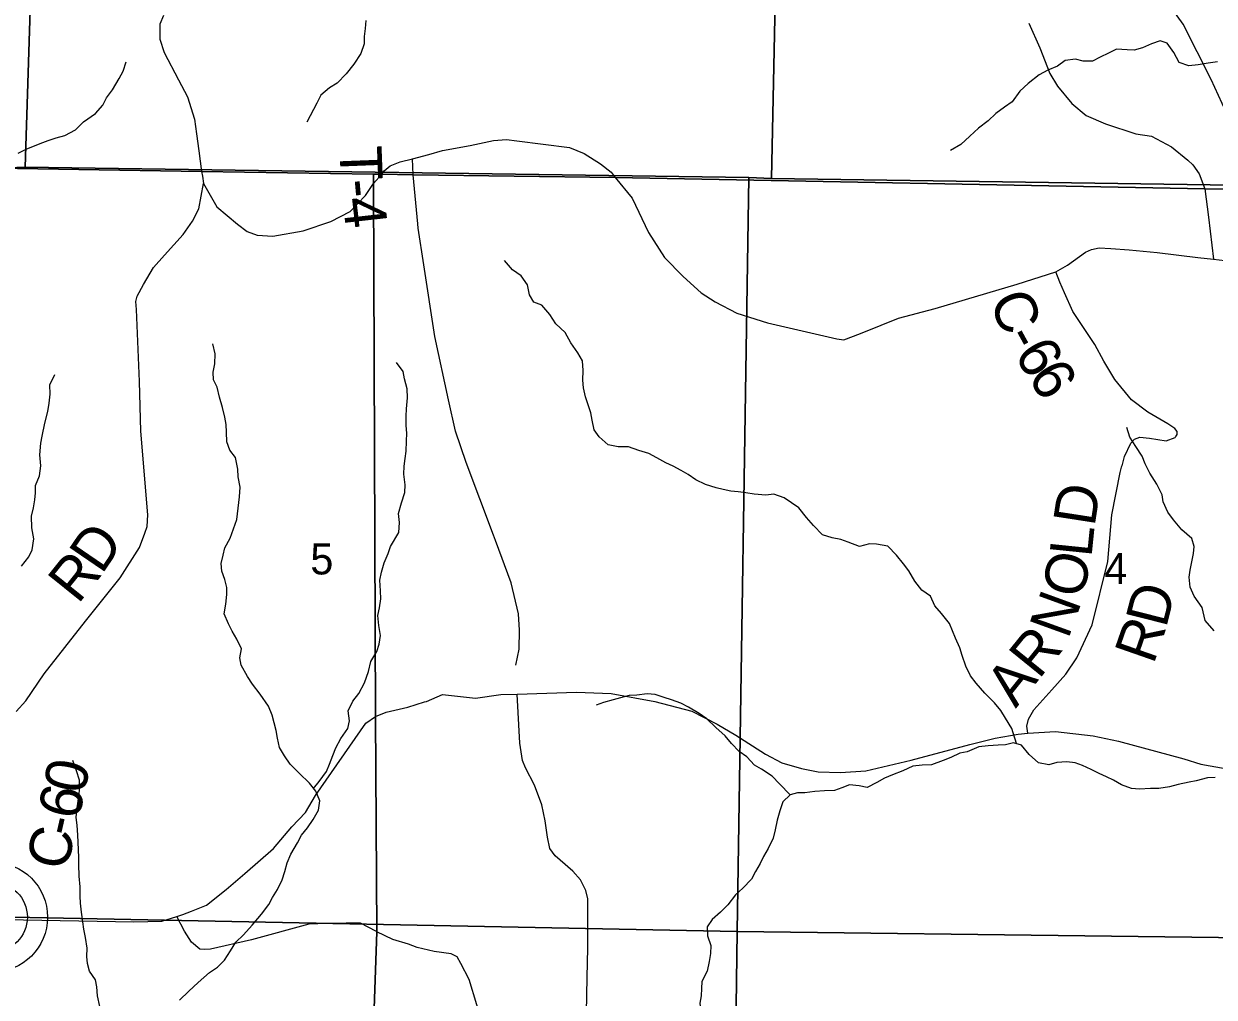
# Model space of a CAD drawing. Extents: x 2043100 to 2470832, y 443715 to 810583.
# Drawn here: x 2231654 to 2240142, y 633122 to 640063 of the extents above; entities that cross this region are included whole.
import ezdxf

# ---------------------------------------------------------------- set-up
doc = ezdxf.new("R2010")
doc.units = 0
for name, color, linetype in [('GM_X_County_Road', 7, 'Continuous'), ('GM_X_County_Road_Text', 7, 'Continuous'), ('GM_X_Interstate_Route', 7, 'Continuous'), ('GM_X_Minor_River', 7, 'Continuous'), ('GM_X_Section', 7, 'Continuous'), ('GM_X_Section_Text', 7, 'Continuous'), ('GM_X_State_Route', 7, 'Continuous'), ('GM_X_Township', 7, 'Continuous'), ('GM_X_Township_Road', 7, 'Continuous'), ('GM_X_Township_Road_Text', 7, 'Continuous'), ('GM_X_Township_ROW', 7, 'Continuous'), ('GM_X_Unincorporated', 7, 'Continuous')]:
    doc.layers.add(name, color=color, linetype=linetype)

msp = doc.modelspace()

# ---------------------------------------------------------------- linework, layer by layer
at = {"layer": 'GM_X_County_Road'}
for points in [[(2232651, 640122.8), (2232625.1, 640060.7), (2232625.1, 639952.5), (2232655.2, 639858.5), (2232757.3, 639664.4), (2232821.5, 639542.1), (2232870.3, 639383.6), (2232886.6, 639278.4), (2232902.9, 639157), (2232922, 639010.4), (2232927.4, 638975.8)], [(2234425.6, 639100.8), (2234542.6, 639130.9), (2234640.2, 639160.3), (2234837.2, 639195.1), (2235003.1, 639231.4), (2235097.1, 639237.6), (2235169.1, 639229.6), (2235544.8, 639180.6), (2235648.6, 639138.3), (2235765.6, 639064.4), (2235841.3, 639004.6), (2235869.8, 638968.1), (2235991.7, 638820.7), (2236108.1, 638575.9), (2236222.7, 638397.3), (2236356.7, 638261), (2236484.5, 638144.7), (2236583.5, 638080), (2236738.7, 638000.1), (2236957.9, 637931.2), (2237297.3, 637852), (2237451.9, 637816.2), (2237500, 637808.8), (2237619.5, 637854.6), (2237766.7, 637912.9), (2237892.1, 637962.8), (2238151.3, 638032.6), (2238737.3, 638205.4), (2239013, 638295.5), (2239094.8, 638342), (2239224.9, 638434.2), (2239266, 638453.3), (2239322.1, 638464.3), (2239405.5, 638461.5), (2239535.5, 638452), (2239735.3, 638431.4), (2240025.2, 638396.8)], [(2232935.3, 638924.7), (2233031.1, 638757.5), (2233176.9, 638633.4), (2233245.7, 638582.4), (2233318.2, 638555.4), (2233430.4, 638549), (2233646, 638586.2), (2233843.2, 638653.2), (2233982.3, 638725.3), (2234089.7, 638839.6), (2234148.8, 638924.2), (2234206.5, 638990.6), (2234223.2, 639013.9), (2234266.2, 639049.8), (2234336.6, 639079.9), (2234425.6, 639100.8)], [(2232927.4, 638975.8), (2232935.3, 638924.7)], [(2231601, 635159), (2231669.9, 635236.1), (2231799.3, 635428.3), (2232094.2, 635803.2), (2232342.1, 636111.3), (2232479.1, 636327.6), (2232517.7, 636430.4), (2232533, 636478.7), (2232539.8, 636560.9), (2232489.3, 637159.1), (2232478.3, 637511.5), (2232457, 638026), (2232454.2, 638082), (2232461.6, 638120.2), (2232508.5, 638205), (2232578.8, 638324.2), (2232657.6, 638413.5), (2232789.6, 638561.7), (2232856.4, 638654.8), (2232903.2, 638743.6), (2232935.3, 638924.7)], [(2240025.2, 638396.8), (2240136.2, 638383.5), (2240420.8, 638350.7), (2240473.8, 638314.4), (2240598, 638293), (2240718.1, 638275.5), (2240814.2, 638272)], [(2239867.4, 637119.6), (2239878.7, 637133.8), (2239878.6, 637155.9), (2239860.5, 637177.8), (2239810.3, 637211.6), (2239667.9, 637293.1), (2239553.4, 637382.7), (2239432.7, 637526.3), (2239354, 637658.2), (2239291.5, 637776), (2239134.3, 638011.7), (2239073.7, 638143.6), (2239041.3, 638219.5), (2239013, 638295.5)], [(2239484.6, 636910.4), (2239503.2, 636977.8), (2239546.8, 637072.2), (2239574.7, 637100.3), (2239610.6, 637116.5), (2239680.7, 637108.9), (2239798.8, 637089.4), (2239862.8, 637113.7), (2239866, 637117.7), (2239867.4, 637119.6)], [(2238812.9, 635004.9), (2238805.3, 635055.6), (2238817, 635103.7), (2238856.8, 635172), (2238984.2, 635312.8), (2239083.8, 635425.5), (2239163.3, 635542), (2239272.3, 635776.9), (2239384.4, 636228.1), (2239410.9, 636562.7), (2239471.6, 636863.5), (2239484.5, 636910.3), (2239484.6, 636910.4)]]:
    msp.add_lwpolyline(points, dxfattribs=at)
at = {"layer": 'GM_X_Interstate_Route'}
msp.add_lwpolyline([(2240394.7, 638771), (2240382.5, 638881.1), (2240303.2, 639267.5), (2240121.4, 639665.5), (2239921.6, 640061.4), (2239486.5, 640666.7), (2238945.3, 641275.5), (2238484.4, 641836.6), (2237995, 642501.7), (2237789.2, 642869.6), (2237609.2, 643317.8), (2237341.9, 644058.2), (2237167.9, 644510.4), (2236925.2, 645114.6), (2236607.5, 645943), (2236281.8, 646755.3), (2236081.5, 647271.5), (2235837.1, 647771.5), (2235579.2, 648157.2), (2235141.7, 648882.8), (2234805.3, 649336.2), (2234488.5, 649938.1), (2234352.9, 650290.3), (2234278.2, 650792.6)], dxfattribs=at)
at = {"layer": 'GM_X_Minor_River'}
for points in [[(2234093.6, 640087.2), (2234087.8, 640029.1), (2234082, 639973), (2234080.1, 639921), (2234056.3, 639850.8), (2234006.6, 639774.6), (2233952.8, 639706.4), (2233889, 639640.1), (2233833.2, 639605.9), (2233771.3, 639553.6), (2233743.5, 639497.5), (2233671.9, 639361.1)], [(2240164.3, 639792), (2240098.3, 639781.7), (2240028.4, 639769.5), (2239960.4, 639763.2), (2239892.4, 639787), (2239854.2, 639858.9), (2239806, 639924.8), (2239756, 639940.7), (2239694.1, 639920.4), (2239630.2, 639892.2), (2239572.3, 639874), (2239520.3, 639877.8), (2239444.3, 639881.5), (2239388.4, 639853.3), (2239328.5, 639825.1), (2239274.6, 639796.9), (2239208.6, 639796.7), (2239152.6, 639810.5), (2239078.7, 639800.2), (2239024.8, 639762), (2238954.9, 639731.8), (2238893, 639699.5), (2238815.3, 639637.2), (2238755.4, 639583), (2238701.7, 639506.7), (2238645.8, 639468.5), (2238586, 639422.3), (2238530.2, 639370), (2238462.4, 639317.8), (2238398.5, 639261.5), (2238334.7, 639203.2), (2238262.9, 639158.9)], [(2231613.2, 639141.7), (2231671.1, 639167.9), (2231771, 639210.3), (2231828.9, 639230.5), (2231884.8, 639248.7), (2231946.7, 639267), (2232022.6, 639307.3), (2232080.4, 639363.5), (2232166.2, 639423.9), (2232218, 639482.1), (2232243.8, 639534.2), (2232285.7, 639592.4), (2232335.4, 639672.7), (2232363.2, 639724.8), (2232383, 639792.9)], [(2238733.2, 634930.1), (2238699.9, 635038.8), (2238653.3, 635112.4), (2238620.8, 635166.2), (2238574.4, 635219.8), (2238505.8, 635289.3), (2238445.2, 635360.8), (2238404.8, 635412.5), (2238372.2, 635482.3), (2238345.6, 635558.1), (2238327.1, 635614), (2238296.5, 635681.7), (2238276.1, 635733.6), (2238253.6, 635787.4), (2238197.1, 635857), (2238150.6, 635912.6), (2238118, 635982.4), (2238057.7, 636023.9), (2238007.2, 636087.5), (2237964.6, 636161.2), (2237926.1, 636212.9), (2237875.6, 636274.5), (2237815.1, 636338), (2237735, 636353.3), (2237683.1, 636354.9), (2237613.3, 636336.3), (2237533, 636367.6), (2237478.9, 636385.2), (2237418.9, 636398.7), (2237348.7, 636418.1), (2237284.2, 636485.5), (2237235.7, 636543.2), (2237181.2, 636610.7), (2237126.9, 636646.3), (2237074.6, 636681.9), (2237002.4, 636709.3), (2236944.6, 636700.8), (2236862.5, 636708.1), (2236802.5, 636717.5), (2236748.5, 636725.1), (2236696.5, 636730.6), (2236640.4, 636742.2), (2236590.3, 636753.7), (2236514.2, 636777.1), (2236445.9, 636810.5), (2236391.6, 636848.1), (2236341.4, 636877.7), (2236283.2, 636909.2), (2236233, 636932.8), (2236166.8, 636968.2), (2236110.5, 636997.8), (2236038.4, 637021.2), (2235966.2, 637046.5), (2235892.3, 637045.9), (2235820.2, 637061.3), (2235755.7, 637116.8), (2235721.3, 637168.5), (2235706.7, 637236.4), (2235698.3, 637288.4), (2235677.8, 637346.2), (2235659.3, 637404.1), (2235644.7, 637468.1), (2235640.2, 637522), (2235643.6, 637590.1), (2235639, 637660.1), (2235604.6, 637715.9), (2235554, 637787.5), (2235513.4, 637861.2), (2235448.8, 637924.7), (2235404.3, 637990.3), (2235347.8, 638055.9), (2235291.6, 638077.4), (2235259.2, 638131.2), (2235244.5, 638201.1), (2235200, 638266.8), (2235139.7, 638308.2), (2235081.1, 638375.8)], [(2233096.8, 637205.8), (2233088.3, 637257.7), (2233071.7, 637327.6), (2233049.1, 637399.5), (2233032.5, 637471.4), (2233008, 637523.2), (2233003.5, 637579.2), (2233017, 637639.4), (2233018.4, 637709.4), (2233001.8, 637781.3)], [(2233720.7, 634610.4), (2233760.7, 634659.8), (2233812.1, 634730.3), (2233833.6, 634784.5), (2233857, 634844.7), (2233878.5, 634899), (2233913.9, 634967.3), (2233965.3, 635037.8), (2233976.8, 635091.9), (2233966.2, 635163.9), (2233999.5, 635232.2), (2234043, 635286.7), (2234084.3, 635363.1), (2234111.6, 635443.4), (2234129, 635515.6), (2234170.3, 635588), (2234187.8, 635638.2), (2234197.3, 635702.3), (2234184.7, 635772.2), (2234178, 635844.2), (2234191.5, 635898.4), (2234199, 635962.5), (2234198.5, 636018.5), (2234193.8, 636094.5), (2234205.3, 636152.7), (2234222.7, 636218.9), (2234252.1, 636285.2), (2234269.6, 636335.3), (2234328.7, 636435.9), (2234332.1, 636506), (2234325.5, 636572), (2234346.9, 636646.2), (2234370.2, 636720.5), (2234373.7, 636774.6), (2234363, 636852.5), (2234366.5, 636908.6), (2234374.1, 636962.7), (2234379.6, 637014.8), (2234383, 637086.8), (2234384.4, 637144.9), (2234380, 637198.9), (2234379.4, 637264.9), (2234382.9, 637317), (2234390.2, 637395.1), (2234387.7, 637459.2), (2234369.1, 637531), (2234358.6, 637583), (2234312.1, 637648.6)], [(2231638.6, 636196.4), (2231690, 636260.9), (2231713.5, 636311.1), (2231726.8, 636389.3), (2231712.1, 636469.2), (2231709.4, 636551.2), (2231722.9, 636611.4), (2231732.4, 636667.5), (2231737.9, 636719.6), (2231737.5, 636771.6), (2231766.8, 636839.9), (2231776.2, 636912.1), (2231767.5, 636990), (2231774.8, 637072.2), (2231784.3, 637122.3), (2231803.5, 637214.5), (2231826.8, 637298.8), (2231836.2, 637358.9), (2231841.7, 637421), (2231839.1, 637489), (2231876.4, 637563.4)], [(2232765.1, 633100), (2232830.5, 633164.6), (2232897.9, 633227.3), (2232979.2, 633298), (2233034.9, 633336.5), (2233086.4, 633385), (2233127.8, 633451.4), (2233167.2, 633513.8), (2233220.7, 633566.3), (2233282.1, 633634.9), (2233349.3, 633713.5), (2233400.7, 633782), (2233428.2, 633832.3), (2233463.7, 633890.7), (2233497.1, 633959), (2233516.6, 634017.2), (2233532, 634079.4), (2233559.4, 634141.7), (2233604.7, 634222.1), (2233634.2, 634276.4), (2233677.7, 634328.8), (2233717.1, 634389.2), (2233754.5, 634455.6), (2233765.9, 634521.7), (2233735.4, 634591.5), (2233690.9, 634649.2), (2233618.3, 634718.6), (2233553.8, 634784.1), (2233513.3, 634843.8), (2233476.8, 634903.5), (2233462.2, 634969.4), (2233453.7, 635023.4), (2233439.3, 635077.3), (2233424.8, 635133.2), (2233398.2, 635197), (2233339.5, 635282.5), (2233284.9, 635354.1), (2233248.5, 635407.8), (2233203.8, 635489.5), (2233195.3, 635541.5), (2233206.8, 635605.6), (2233174.2, 635675.4), (2233139.7, 635731.1), (2233113.3, 635784.9), (2233082.6, 635856.7), (2233094, 635924.8), (2233101.4, 635993), (2233101, 636043), (2233086.5, 636100.9), (2233066, 636158.8), (2233061.5, 636214.8), (2233075, 636274.9), (2233088.5, 636325.1), (2233125.9, 636395.5), (2233149.3, 636461.7), (2233172.7, 636528), (2233183.9, 636610.1), (2233193.2, 636690.2), (2233196.6, 636758.3), (2233182, 636832.2), (2233179.5, 636888.3), (2233164.8, 636970.2), (2233122.4, 637021.9), (2233101.8, 637081.7), (2233099.2, 637151.7), (2233096.8, 637205.8)], [(2240142.7, 635733.7), (2240078.1, 635807.2), (2240057.3, 635901.1), (2239998.6, 635980.6), (2239970.1, 636046.4), (2239963.5, 636116.4), (2239971, 636166.5), (2239993.9, 636286.8), (2239999.5, 636336.9), (2239983, 636392.8), (2239910.5, 636454.2), (2239851.9, 636525.7), (2239811.5, 636579.4), (2239778.9, 636653.2), (2239770.4, 636705.1), (2239733.8, 636780.9), (2239683.1, 636858.5), (2239648.6, 636926.2), (2239628.1, 636980.1), (2239583.5, 637049.8), (2239541, 637115.4), (2239518.4, 637183.3)], [(2237119.2, 634564.8), (2237042.6, 634644.2), (2236990.1, 634697.8), (2236913.8, 634747.2), (2236863.5, 634776.8), (2236809.1, 634836.3), (2236754.8, 634873.9), (2236700.3, 634931.4), (2236653.9, 634985.1), (2236589.4, 635044.6), (2236524.9, 635106), (2236468.6, 635145.6), (2236394.2, 635191), (2236340, 635218.5), (2236271.9, 635241.9), (2236219.8, 635259.5), (2236155.6, 635281), (2236099.6, 635284.5), (2236025.7, 635275.8), (2235969.8, 635273.4), (2235908, 635256.8), (2235856.2, 635242.4), (2235786.4, 635223.7), (2235734.6, 635205.3)], [(2240149.9, 634689), (2240094, 634686.6), (2240014.2, 634663.9), (2239962.3, 634655.4), (2239884.5, 634638.7), (2239822.7, 634622.2), (2239746.9, 634609.5), (2239686.9, 634611), (2239609, 634604.3), (2239553, 634609.8), (2239480.8, 634637.2), (2239424.6, 634668.8), (2239374.4, 634692.4), (2239322.3, 634715.9), (2239264.1, 634745.4), (2239201.8, 634774.9), (2239151.7, 634792.5), (2239091.7, 634800), (2239019.8, 634795.4), (2238964, 634778.9), (2238889.9, 634792.3), (2238823.4, 634851.7), (2238768.9, 634919.3), (2238710.8, 634936.8), (2238653, 634922.3), (2238601, 634919.8), (2238531.1, 634913.2), (2238463.2, 634906.6), (2238381.6, 634871.9), (2238327.7, 634861.4), (2238264, 634830.9), (2238208.3, 634810.4), (2238126.6, 634777.7), (2238060.7, 634777.1), (2237992.8, 634770.5), (2237921.1, 634735.9), (2237847.4, 634707.2), (2237791.7, 634684.7), (2237736, 634652.2), (2237668.4, 634617.6), (2237610.3, 634629.1), (2237542.3, 634636.5), (2237486.5, 634614), (2237434.7, 634595.6), (2237362.8, 634592.9), (2237294.9, 634588.3), (2237223, 634579.7), (2237171.1, 634579.3), (2237119.2, 634564.8), (2237065.7, 634514.3), (2237044.3, 634450.1), (2237026.9, 634383.9), (2237011.5, 634315.7), (2236998, 634255.5), (2236962.7, 634183.2), (2236927.2, 634124.8), (2236903.7, 634074.6), (2236870.2, 634018.3), (2236842.7, 633964), (2236781.3, 633899.4), (2236729.8, 633853)], [(2232195.9, 633055), (2232179.2, 633130.9), (2232174.7, 633194.9), (2232166.2, 633246.9), (2232123.7, 633306.6), (2232107.3, 633362.5), (2232102.8, 633412.5), (2232106.3, 633472.5), (2232093.6, 633548.5), (2232083.1, 633606.4), (2232074.6, 633660.4), (2232066.1, 633728.4), (2232059.5, 633792.4), (2232057.1, 633842.4), (2232056.5, 633908.4), (2232049.8, 633984.4), (2232047.1, 634068.4), (2232046.6, 634118.5), (2232044.2, 634172.5), (2232041.7, 634228.5), (2232039.2, 634278.5), (2232034.6, 634348.5), (2232028.1, 634404.5), (2232031.7, 634454.6), (2232041.1, 634518.7), (2232050.4, 634596.8), (2232051.8, 634668.9), (2232029.2, 634736.8), (2232004.6, 634808.6)], [(2236729.8, 633853), (2236674.5, 633780.4), (2236621, 633727.9), (2236561.5, 633675.4), (2236525.9, 633623), (2236528.5, 633559), (2236553.1, 633491.2), (2236551.6, 633433.1), (2236542.1, 633377), (2236526.7, 633306.8), (2236489.4, 633234.4), (2236485.8, 633184.4), (2236484.3, 633132.3), (2236474.8, 633080.2), (2236481.4, 633010.2), (2236494, 632940.3)]]:
    msp.add_lwpolyline(points, dxfattribs=at)
at = {"layer": 'GM_X_Section'}
for points in [[(2231831, 644275.3), (2231663.3, 639041.5), (2231545.3, 639036.3), (2226228.4, 639113.1), (2226281.7, 644387.8)], [(2237095.6, 644222), (2236986.2, 638960.8), (2236824, 638967.1), (2231663.3, 639041.5), (2231831, 644275.3)], [(2242378.2, 644174.8), (2242269, 638887.7), (2242088.5, 638885.8), (2236986.2, 638960.8), (2237095.6, 644222)], [(2231545.3, 639036.3), (2231663.3, 639041.5), (2236824, 638967.1), (2236741.5, 633590.1), (2231454.4, 633695.2)], [(2236824, 638967.1), (2236986.2, 638960.8), (2242088.5, 638885.8), (2242078.3, 633523.6), (2236741.5, 633590.1)], [(2231454.4, 633695.2), (2236741.5, 633590.1), (2236670.8, 628461.4), (2231333.8, 628547.9)], [(2236741.5, 633590.1), (2242078.3, 633523.6), (2242002.4, 628310.7), (2236670.8, 628461.4)]]:
    msp.add_lwpolyline(points, close=True, dxfattribs=at)
at = {"layer": 'GM_X_State_Route'}
for points in [[(2234512.3, 635227.3), (2234525.3, 635231.3), (2234639.7, 635280.4), (2234874.4, 635253.4), (2235054.6, 635279.8), (2235171.8, 635281.7), (2235595.3, 635297.4), (2235841.5, 635288.6), (2236153.6, 635231.4), (2236417.4, 635161), (2236597.6, 635068.7), (2236730.6, 634990.6), (2236943.8, 634854.3), (2237058.1, 634792.7), (2237198.8, 634753.1), (2237317.5, 634729), (2237477.9, 634723.7), (2237657.7, 634735.7), (2237980.3, 634812.8), (2238400.1, 634923.1), (2238579.2, 634970.1), (2238744.8, 634997.8), (2238812.9, 635004.9), (2239010, 635017), (2239278.2, 634986.3), (2239460.4, 634947.2), (2239924.9, 634822.4), (2240045.8, 634784.6), (2240219.6, 634752.5)], [(2232851.1, 633736.3), (2232957.1, 633777.6), (2233096.7, 633890.9), (2233230.3, 634004), (2233434.5, 634182.7), (2233565.3, 634335.8), (2233663, 634440.1), (2233734.5, 634559.9), (2234092.1, 635075.3), (2234162.8, 635122.7), (2234237, 635154.1), (2234392.2, 635190.6), (2234512.3, 635227.3)], [(2231420, 633677.9), (2231522.5, 633676.1), (2232439.3, 633660.1), (2232639.4, 633664.5), (2232745.6, 633698.2), (2232788.4, 633711.8), (2232851.1, 633736.3)]]:
    msp.add_lwpolyline(points, dxfattribs=at)
at = {"layer": 'GM_X_Township'}
for points in [[(2247707.5, 648351.7), (2247643.8, 645707.3), (2247545.4, 640176.7), (2247504, 638792.8), (2245281.8, 638809), (2244966.2, 638818.3), (2244403.6, 638834.8), (2244077.4, 638844.4), (2243764.8, 638853.6), (2243266.9, 638868.3), (2242283.4, 638880.3), (2242084.2, 638871.4), (2240382.5, 638881.1), (2240076, 638887.1), (2235869.8, 638968.1), (2234430.6, 638986.4), (2234206.5, 638990.6), (2234148.5, 638991.7), (2232922, 639010.4), (2230294.1, 639053.5)], [(2209977.9, 623419.1), (2210251.5, 634590.7), (2210261.7, 635532.1), (2210323.9, 639312.1), (2210330.4, 639454.1), (2210326.8, 639537.9), (2216075, 639353.1), (2219619.4, 639265.9), (2220927.1, 639237.4), (2223066.2, 639196.9), (2225149.7, 639137.8), (2227395.5, 639101), (2230294.1, 639053.5), (2232922, 639010.4), (2234148.5, 638991.7), (2234148.8, 638924.2), (2234162.8, 635122.7), (2234171.5, 633589.1), (2234072.5, 630720.1)], [(2234072.5, 630720.1), (2234171.5, 633589.1), (2234162.8, 635122.7), (2234148.8, 638924.2), (2234148.5, 638991.7), (2234206.5, 638990.6), (2234430.6, 638986.4), (2235869.8, 638968.1), (2240076, 638887.1), (2240382.5, 638881.1), (2242084.2, 638871.4), (2242283.4, 638880.3), (2243266.9, 638868.3), (2243764.8, 638853.6), (2244077.4, 638844.4), (2244403.6, 638834.8), (2244966.2, 638818.3), (2245281.8, 638809), (2247504, 638792.8), (2247807.2, 638785), (2252195.8, 638709.3), (2255374.8, 638639.7)]]:
    msp.add_lwpolyline(points, dxfattribs=at)
at = {"layer": 'GM_X_Township_Road'}
for points in [[(2238820.4, 640067.4), (2238897.6, 639891.8), (2238970.9, 639708.2), (2239023.5, 639618.5), (2239126.3, 639495.1), (2239228.9, 639409.8), (2239367.2, 639350.8), (2239583.6, 639278.4), (2239694.3, 639260.6), (2239836.6, 639185.4), (2239952.9, 639091), (2239989.8, 639056.8), (2240033.6, 638993.8), (2240076, 638887.1), (2240100.4, 638683.1)], [(2234462.6, 638637.6), (2234430.6, 638986.4), (2234425.6, 639100.8)], [(2240100.4, 638683.1), (2240136.2, 638383.5)], [(2235296, 634634), (2235295.9, 634634.1), (2235230.8, 634757.7), (2235210.3, 634809.6), (2235191.2, 634933.6), (2235171.8, 635281.7)], [(2235666.5, 633010.8), (2235670.2, 633263.2), (2235676.4, 633473.6), (2235676.2, 633722), (2235675.3, 633822.2), (2235660.8, 633882.2), (2235624.1, 633958), (2235569.5, 634021.6), (2235478.8, 634098.9), (2235442.5, 634130.6), (2235406, 634182.4), (2235387.3, 634262.3), (2235372.2, 634380.4), (2235347.2, 634494.3), (2235296, 634634)], [(2234168.5, 633590.7), (2234053.8, 633649.4), (2233953.6, 633650.4), (2233815.5, 633647.2), (2233685.6, 633643.2), (2233277.3, 633530.7), (2232986.5, 633465.4), (2232944.5, 633461), (2232910.4, 633464.7), (2232849.9, 633514.2), (2232801.2, 633591.9), (2232745.6, 633698.2)], [(2235646.2, 632587.9), (2235537.9, 632605), (2235391.3, 632669.8), (2235192.6, 632730.1), (2235110.3, 632759.4), (2235035.9, 632798.8), (2234973.3, 632856.3), (2234924.5, 632944), (2234885.4, 633067.9), (2234828.7, 633248.8), (2234770.1, 633362.8), (2234743.9, 633409), (2234702.4, 633430.6), (2234579.8, 633447.7), (2234459.5, 633476.7), (2234397.3, 633499.9), (2234286.4, 633532.3), (2234171.5, 633589.1), (2234168.5, 633590.7)]]:
    msp.add_lwpolyline(points, dxfattribs=at)
at = {"layer": 'GM_X_Township_ROW'}
msp.add_lwpolyline([(2235163, 635488.4), (2235185.3, 635604.7), (2235188.1, 635738.9), (2235181.1, 635855), (2235129.1, 636076.9), (2235017.9, 636378.6), (2235004, 636416.3), (2234809.4, 636935.4), (2234731.3, 637157.1), (2234681.3, 637381), (2234585.3, 637832.9), (2234506.7, 638345), (2234465.4, 638606.8), (2234462.6, 638637.6)], dxfattribs=at)
at = {"layer": 'GM_X_Unincorporated'}
for radius in [392.8, 249]:
    msp.add_circle((2231430.6, 633693), radius, dxfattribs=at)

# ---------------------------------------------------------------- texts
at = {"layer": 'GM_X_County_Road_Text'}
for s, rotation, p in [('C', 291.93114, (2238535, 638092)), ('-', 298.74286, (2238643.7, 637828.3)), ('6', 301.36569, (2238710.5, 637707.2)), ('6', 301.84973, (2238808.1, 637547.1)), ('D', 81.23417, (2239288.7, 636472.6)), ('D', 55.66798, (2232209.8, 636130.9)), ('L', 84.14453, (2239266.3, 636253.3)), ('R', 51.20243, (2232040.5, 635918.7)), ('O', 77.26995, (2239201.8, 635957)), ('D', 75.79097, (2239798.2, 635748.6)), ('N', 70.03896, (2239100, 635669.2)), ('R', 70.73684, (2239708.7, 635488.7)), ('R', 50.97751, (2238891.5, 635383.4)), ('A', 51.35213, (2238726.9, 635177.6)), ('0', 78.33705, (2232085.1, 634563.7)), ('6', 77.38055, (2232043.5, 634378)), ('-', 76.91098, (2232015, 634255.4)), ('C', 76.75232, (2231958.3, 634014.7))]:
    msp.add_text(s, height=300, rotation=rotation, dxfattribs=at).set_placement(p)
at = {"layer": 'GM_X_Section_Text'}
for s, p in [('5', (2233697.2, 636136.6)), ('4', (2239357.8, 636067.9))]:
    msp.add_text(s, height=220.8, rotation=0.00001, dxfattribs=at).set_placement(p)
at = {"layer": 'GM_X_Township_Road_Text'}
for s, rotation, p in [('T', 272.23341, (2233904.9, 639186.4)), ('-', 275.1111, (2233914.7, 638945.8)), ('4', 276.43375, (2233926.4, 638815.6))]:
    msp.add_text(s, height=300, rotation=rotation, dxfattribs=at).set_placement(p)

doc.saveas('drawing.dxf')
